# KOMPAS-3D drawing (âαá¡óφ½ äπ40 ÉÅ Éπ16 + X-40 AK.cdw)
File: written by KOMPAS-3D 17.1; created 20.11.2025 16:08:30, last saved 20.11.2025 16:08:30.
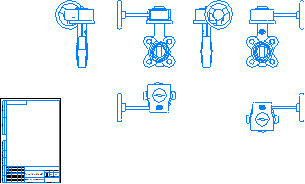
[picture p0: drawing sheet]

Sheet 1: A4, portrait

Title block, sheet 1: name: Гранвэл Ду40; material: Сталь 10  ГОСТ 1050-88; mass: 5,2; sheets: 1; sheet format: A4

Views: Вид 1, Спереди, Проекционный вид 2, Проекционный вид 3, Проекционный вид 4, Проекционный вид 5, Проекционный вид 6
Referenced files in \\adlc.lan\data\АДЛ_ПКД\3D-модели\ADL production\Дисковые поворотные затворы ГРАНВЭЛ\с резьбовыми проушинами с китайским редуктором Ру 16\KOMPAS 3D\: Гранвэл Ду40 РП Ру16 + X-40 AK.m3d
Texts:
  Andrey
  АДЛ
Dimensions and other numbers on the sheet: 1:1; 1; 5,2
